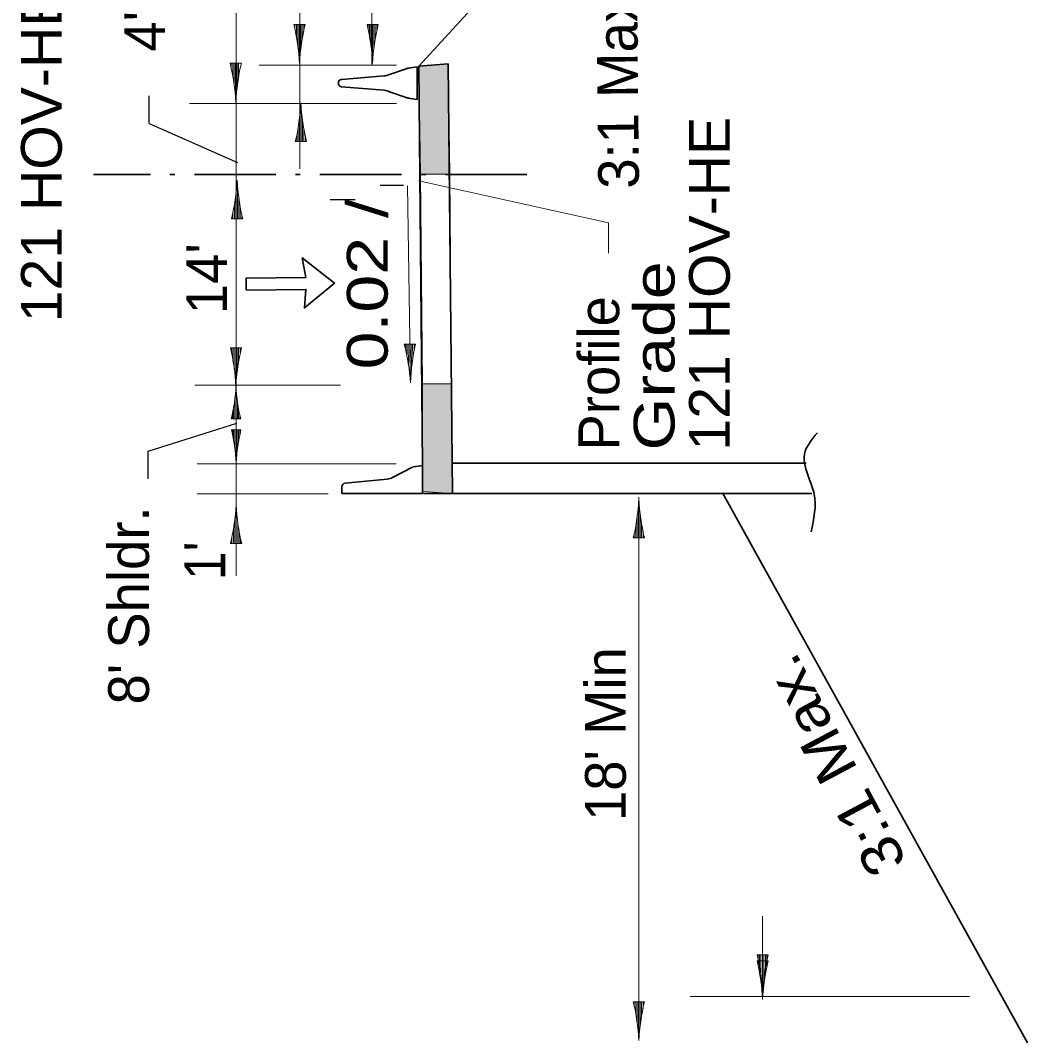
# Model space of a CAD drawing. Extents: x 2363427 to 2368559, y 6957299 to 6980140.
# Drawn here: x 2365078.3 to 2365424.5, y 6964606.4 to 6964957.4 of the extents above; entities that cross this region are included whole.
import ezdxf
from ezdxf.enums import TextEntityAlignment as Align

# ---------------------------------------------------------------- set-up
doc = ezdxf.new("R2010")
doc.units = 0
doc.header["$LTSCALE"] = 5.6
doc.linetypes.add('DOT_DASHED', pattern=[7.7, 5, -1.2, 0.3, -1.2])
doc.layers.add('3', color=7, linetype='Continuous', lineweight=35)
doc.layers.add('4', color=7, linetype='Continuous', lineweight=13)

msp = doc.modelspace()

# ---------------------------------------------------------------- hatches: boundary and pattern name
at = {"layer": '3'}
for points in [[(2365215.222, 6964941.608), (2365225.378, 6964942.446), (2365225.904, 6964904.586), (2365215.863, 6964904.586)], [(2365216.491, 6964795.461), (2365226.814, 6964794.766), (2365226.531, 6964832.463), (2365216.491, 6964832.463)]]:
    msp.add_hatch(color=256, dxfattribs=at).paths.add_polyline_path(points)

# ---------------------------------------------------------------- linework, layer by layer
at = {"layer": '3', "lineweight": 13}
for p, q in [((2365174.345, 6964906.409), (2365174.345, 6965009.032)), ((2365199.111, 6964942.054), (2365199.111, 6964990.853)), ((2365152.449, 6964766.446), (2365152.449, 6964981.39)), ((2365280.421, 6964887.841), (2365215.226, 6964902.184)), ((2365280.421, 6964887.841), (2365280.421, 6964877.381))]:
    msp.add_line(p, q, dxfattribs=at)
at = {"layer": '3'}
for p, q in [((2365259.357, 6964989.862), (2365215.222, 6964941.608)), ((2365205.179, 6964938.845), (2365211.293, 6964940.886)), ((2365211.457, 6964940.952), (2365211.467, 6964940.976)), ((2365214.73, 6964941.464), (2365211.467, 6964940.976)), ((2365214.73, 6964941.464), (2365211.664, 6964941.006)), ((2365214.73, 6964941.464), (2365214.73, 6964935.84)), ((2365226.814, 6964794.766), (2365225.378, 6964942.446)), ((2365187.66, 6964936.24), (2365187.66, 6964935.84)), ((2365187.66, 6964935.439), (2365187.66, 6964935.84)), ((2365203.391, 6964938.316), (2365188.687, 6964937.081)), ((2365214.73, 6964930.214), (2365214.73, 6964935.84)), ((2365203.391, 6964933.363), (2365188.687, 6964934.598)), ((2365205.179, 6964932.834), (2365211.293, 6964930.792)), ((2365211.457, 6964930.728), (2365211.467, 6964930.702)), ((2365214.73, 6964930.214), (2365211.467, 6964930.702)), ((2365214.73, 6964930.214), (2365211.664, 6964930.674)), ((2365176.449, 6964864.892), (2365155.944, 6964864.696)), ((2365206.257, 6964800.286), (2365213.091, 6964803.8)), ((2365213.259, 6964803.866), (2365213.269, 6964803.892)), ((2365216.557, 6964804.384), (2365216.557, 6964794.754)), ((2365226.713, 6964805.222), (2365348.364, 6964805.222)), ((2365189.943, 6964798.292), (2365204.426, 6964799.744)), ((2365188.837, 6964794.754), (2365188.837, 6964797.068)), ((2365216.557, 6964794.754), (2365188.837, 6964794.754)), ((2365226.892, 6964794.766), (2365216.889, 6964794.766)), ((2365226.892, 6964794.766), (2365350.332, 6964794.766)), ((2365424.46, 6964605.922), (2365319.67, 6964794.944))]:
    msp.add_line(p, q, dxfattribs=at)
at = {"layer": '3', "linetype": 'DOT_DASHED'}
msp.add_line((2365252.369, 6964904.416), (2365103.492, 6964904.416), dxfattribs=at)
at = {"layer": '3', "lineweight": 13}
for points in [[(2365215.222, 6964941.608), (2365225.378, 6964942.446), (2365225.904, 6964904.586), (2365215.863, 6964904.586)], [(2365216.491, 6964832.463), (2365226.531, 6964832.463), (2365225.904, 6964904.586), (2365215.863, 6964904.586)], [(2365216.491, 6964795.461), (2365226.814, 6964794.766), (2365226.531, 6964832.463), (2365216.491, 6964832.463)]]:
    msp.add_lwpolyline(points, close=True, dxfattribs=at)
at = {"layer": '3'}
for points in [[(2365216.557, 6964804.384), (2365215.222, 6964941.608), (2365225.378, 6964942.446)], [(2365176.449, 6964864.892), (2365175.917, 6964858.576), (2365186.304, 6964867.112), (2365175.204, 6964875.714), (2365176.412, 6964868.986)], [(2365176.412, 6964868.986), (2365155.907, 6964868.792), (2365155.944, 6964864.696)], [(2365213.471, 6964803.922), (2365216.611, 6964804.392), (2365213.269, 6964803.892)]]:
    msp.add_lwpolyline(points, dxfattribs=at)
msp.add_lwpolyline([(2365186.304, 6964867.112), (2365175.917, 6964858.576), (2365176.449, 6964864.892), (2365155.944, 6964864.696), (2365155.907, 6964868.792), (2365176.412, 6964868.986), (2365175.204, 6964875.714)], close=True, dxfattribs=at)
for centre, radius, start, end in [((2365211.842, 6964939.82), 1.2, 98.51269, 117.22516), ((2365188.807, 6964935.888), 1.2, 95.72178, 162.90786), ((2365202.891, 6964943.292), 5, 275.73538, 297.22872), ((2365188.807, 6964935.792), 1.2, 197.09214, 264.27822), ((2365202.891, 6964928.388), 5, 62.77128, 84.26462), ((2365211.842, 6964931.86), 1.2, 242.77484, 261.48731), ((2365203.915, 6964804.839), 5.12, 275.73538, 297.22872), ((2365190.066, 6964797.069), 1.229, 95.72178, 180)]:
    msp.add_arc(centre, radius, start, end, dxfattribs=at)
msp.add_spline([(2365350.035, 6964781.584), (2365351.147, 6964794.552), (2365349.293, 6964800.11), (2365347.81, 6964808.262), (2365352.259, 6964815.672)], degree=3, dxfattribs=at)
at = {"layer": '4'}
for p, q in [((2365172.333, 6964955.924), (2365176.163, 6964955.924)), ((2365172.683, 6964955.924), (2365172.683, 6964954.338)), ((2365173.183, 6964955.924), (2365173.183, 6964951.647)), ((2365173.683, 6964955.924), (2365173.683, 6964948.574)), ((2365174.183, 6964955.924), (2365174.183, 6964943.36)), ((2365174.683, 6964955.924), (2365174.683, 6964947.314)), ((2365175.183, 6964955.924), (2365175.183, 6964951.062)), ((2365175.683, 6964955.924), (2365175.683, 6964953.542)), ((2365197.459, 6964955.924), (2365201.289, 6964955.924)), ((2365197.809, 6964955.924), (2365197.809, 6964954.338)), ((2365198.309, 6964955.924), (2365198.309, 6964951.647)), ((2365198.809, 6964955.924), (2365198.809, 6964948.574)), ((2365199.309, 6964955.924), (2365199.309, 6964943.36)), ((2365199.809, 6964955.924), (2365199.809, 6964947.314)), ((2365200.309, 6964955.924), (2365200.309, 6964951.062)), ((2365200.809, 6964955.924), (2365200.809, 6964953.542)), ((2365150.437, 6964942.648), (2365154.267, 6964942.648)), ((2365150.787, 6964942.648), (2365150.787, 6964941.062)), ((2365151.287, 6964942.648), (2365151.287, 6964938.371)), ((2365151.787, 6964942.648), (2365151.787, 6964935.298)), ((2365152.287, 6964942.648), (2365152.287, 6964930.084)), ((2365152.787, 6964942.648), (2365152.787, 6964934.038)), ((2365153.287, 6964942.648), (2365153.287, 6964937.786)), ((2365207.597, 6964942.054), (2365160.427, 6964942.054)), ((2365207.597, 6964928.777), (2365136.481, 6964928.777)), ((2365174.781, 6964915.704), (2365174.781, 6964928.268)), ((2365174.281, 6964915.704), (2365174.281, 6964924.314)), ((2365175.281, 6964915.704), (2365175.281, 6964923.054)), ((2365173.281, 6964915.704), (2365173.281, 6964918.086)), ((2365173.781, 6964915.704), (2365173.781, 6964920.566)), ((2365175.781, 6964915.704), (2365175.781, 6964919.981)), ((2365176.631, 6964915.704), (2365172.801, 6964915.704)), ((2365176.281, 6964915.704), (2365176.281, 6964917.289)), ((2365152.885, 6964889.152), (2365152.885, 6964901.716)), ((2365212.4, 6964832.806), (2365211.326, 6964900.522)), ((2365152.385, 6964889.152), (2365152.385, 6964897.762)), ((2365151.885, 6964889.152), (2365151.885, 6964894.014)), ((2365153.385, 6964889.152), (2365153.385, 6964896.502)), ((2365151.385, 6964889.152), (2365151.385, 6964891.534)), ((2365153.885, 6964889.152), (2365153.885, 6964893.428)), ((2365154.385, 6964889.152), (2365154.385, 6964890.736)), ((2365154.735, 6964889.152), (2365150.905, 6964889.152)), ((2365150.491, 6964844.872), (2365154.321, 6964844.872)), ((2365150.841, 6964844.872), (2365150.841, 6964843.287)), ((2365151.341, 6964844.872), (2365151.341, 6964840.596)), ((2365151.841, 6964844.872), (2365151.841, 6964837.522)), ((2365152.341, 6964844.872), (2365152.341, 6964832.308)), ((2365152.841, 6964844.872), (2365152.841, 6964836.262)), ((2365153.341, 6964844.872), (2365153.341, 6964840.01)), ((2365153.841, 6964844.872), (2365153.841, 6964842.49)), ((2365210.274, 6964846.084), (2365214.103, 6964846.146)), ((2365210.624, 6964846.09), (2365210.649, 6964844.506)), ((2365211.124, 6964846.098), (2365211.192, 6964841.822)), ((2365211.624, 6964846.106), (2365211.74, 6964838.758)), ((2365212.124, 6964846.114), (2365212.323, 6964833.552)), ((2365212.624, 6964846.122), (2365212.76, 6964837.514)), ((2365213.123, 6964846.13), (2365213.201, 6964841.268)), ((2365213.623, 6964846.138), (2365213.661, 6964843.756)), ((2365188.367, 6964831.96), (2365138.254, 6964831.96)), ((2365152.472, 6964820.394), (2365152.472, 6964831.074)), ((2365152.047, 6964820.394), (2365152.047, 6964827.712)), ((2365151.622, 6964820.394), (2365151.622, 6964824.526)), ((2365152.897, 6964820.394), (2365152.897, 6964826.642)), ((2365153.322, 6964820.394), (2365153.322, 6964824.03)), ((2365154.044, 6964820.394), (2365150.789, 6964820.394)), ((2365151.197, 6964820.394), (2365151.197, 6964822.418)), ((2365153.747, 6964820.394), (2365153.747, 6964821.742)), ((2365150.879, 6964816.604), (2365154.135, 6964816.604)), ((2365151.177, 6964816.604), (2365151.177, 6964815.257)), ((2365151.601, 6964816.604), (2365151.601, 6964812.97)), ((2365152.027, 6964816.604), (2365152.027, 6964810.357)), ((2365152.451, 6964816.604), (2365152.451, 6964805.924)), ((2365152.877, 6964816.604), (2365152.877, 6964809.286)), ((2365153.301, 6964816.604), (2365153.301, 6964812.472)), ((2365153.727, 6964816.604), (2365153.727, 6964814.58)), ((2365207.473, 6964804.942), (2365139.048, 6964804.942)), ((2365184.059, 6964794.678), (2365139.048, 6964794.678)), ((2365290.803, 6964779.513), (2365290.803, 6964792.077)), ((2365290.869, 6964606.718), (2365290.868, 6964793.518)), ((2365152.526, 6964777.568), (2365152.526, 6964790.132)), ((2365152.026, 6964777.568), (2365152.026, 6964786.178)), ((2365153.026, 6964777.568), (2365153.026, 6964784.918)), ((2365290.303, 6964779.513), (2365290.303, 6964786.863)), ((2365291.303, 6964779.513), (2365291.303, 6964788.122)), ((2365151.526, 6964777.568), (2365151.526, 6964782.43)), ((2365153.526, 6964777.568), (2365153.526, 6964781.844)), ((2365289.803, 6964779.513), (2365289.803, 6964783.79)), ((2365291.803, 6964779.513), (2365291.803, 6964784.375)), ((2365292.303, 6964779.513), (2365292.303, 6964781.894)), ((2365151.026, 6964777.568), (2365151.026, 6964779.95)), ((2365154.026, 6964777.568), (2365154.026, 6964779.152)), ((2365288.953, 6964779.513), (2365292.783, 6964779.513)), ((2365289.303, 6964779.513), (2365289.303, 6964781.098)), ((2365154.376, 6964777.568), (2365150.546, 6964777.568)), ((2365333.404, 6964621.277), (2365333.404, 6964649.497)), ((2365331.489, 6964636.229), (2365335.319, 6964636.229)), ((2365331.489, 6964634.139), (2365335.319, 6964634.139)), ((2365331.839, 6964636.229), (2365331.839, 6964634.645)), ((2365331.839, 6964634.139), (2365331.839, 6964632.553)), ((2365332.339, 6964636.229), (2365332.339, 6964631.953)), ((2365332.339, 6964634.139), (2365332.339, 6964629.861)), ((2365332.839, 6964636.229), (2365332.839, 6964628.879)), ((2365332.839, 6964634.139), (2365332.839, 6964626.789)), ((2365333.339, 6964636.229), (2365333.339, 6964623.665)), ((2365333.339, 6964634.139), (2365333.339, 6964621.575)), ((2365333.839, 6964636.229), (2365333.839, 6964627.619)), ((2365333.839, 6964634.139), (2365333.839, 6964625.529)), ((2365334.339, 6964636.229), (2365334.339, 6964631.367)), ((2365334.339, 6964634.139), (2365334.339, 6964629.277)), ((2365334.839, 6964636.229), (2365334.839, 6964633.847)), ((2365334.839, 6964634.139), (2365334.839, 6964631.757)), ((2365288.954, 6964620.03), (2365292.784, 6964620.03)), ((2365289.304, 6964620.03), (2365289.304, 6964618.445)), ((2365289.804, 6964620.03), (2365289.804, 6964615.754)), ((2365290.304, 6964620.03), (2365290.304, 6964612.68)), ((2365290.804, 6964620.03), (2365290.804, 6964607.466)), ((2365291.304, 6964620.03), (2365291.304, 6964611.42)), ((2365291.804, 6964620.03), (2365291.804, 6964615.168)), ((2365292.304, 6964620.03), (2365292.304, 6964617.648)), ((2365404.537, 6964621.87), (2365308.474, 6964621.87))]:
    msp.add_line(p, q, dxfattribs=at)
at = {"layer": '4', "lineweight": 25}
for p, q in [((2365122.636, 6964921.9), (2365122.636, 6964931.486)), ((2365122.636, 6964921.9), (2365152.889, 6964908.562)), ((2365201.952, 6964900.798), (2365209.984, 6964900.798)), ((2365193.381, 6964895.659), (2365184.81, 6964895.659)), ((2365122.227, 6964809.33), (2365152.68, 6964818.904)), ((2365122.227, 6964799.746), (2365122.227, 6964809.33))]:
    msp.add_line(p, q, dxfattribs=at)
at = {"layer": '4'}
for centre, radius, start, end in [((2365102.125, 6964939.03), 72.212, 2.84356, 13.52961), ((2365246.372, 6964939.03), 72.212, 166.47039, 177.15644), ((2365127.252, 6964939.03), 72.212, 2.84356, 13.52961), ((2365271.499, 6964939.03), 72.212, 166.47039, 177.15644), ((2365080.229, 6964925.754), 72.212, 2.84356, 13.52961), ((2365224.476, 6964925.754), 72.212, 166.47039, 177.15644), ((2365102.592, 6964932.599), 72.212, 346.47039, 357.15644), ((2365246.839, 6964932.599), 72.212, 182.84356, 193.52961), ((2365080.696, 6964906.046), 72.212, 346.47039, 357.15644), ((2365224.943, 6964906.046), 72.212, 182.84356, 193.52961), ((2365080.283, 6964827.979), 72.212, 2.84356, 13.52961), ((2365224.53, 6964827.979), 72.212, 166.47039, 177.15644), ((2365140.343, 6964828.08), 72.212, 3.7522, 14.43825), ((2365284.572, 6964830.368), 72.212, 167.37903, 178.06508), ((2365091.111, 6964834.755), 61.381, 346.47039, 357.15644), ((2365213.721, 6964834.755), 61.381, 182.84356, 193.52961), ((2365091.203, 6964802.245), 61.381, 2.84356, 13.52961), ((2365213.813, 6964802.245), 61.381, 166.47039, 177.15644), ((2365218.745, 6964796.408), 72.212, 346.47039, 357.15644), ((2365362.992, 6964796.408), 72.212, 182.84356, 193.52961), ((2365080.337, 6964794.462), 72.212, 346.47039, 357.15644), ((2365224.584, 6964794.462), 72.212, 182.84356, 193.52961), ((2365261.282, 6964619.336), 72.212, 2.84356, 13.52961), ((2365261.282, 6964617.245), 72.212, 2.84356, 13.52961), ((2365405.529, 6964619.336), 72.212, 166.47039, 177.15644), ((2365405.529, 6964617.245), 72.212, 166.47039, 177.15644), ((2365218.746, 6964603.137), 72.212, 2.84356, 13.52961), ((2365362.993, 6964603.137), 72.212, 166.47039, 177.15644)]:
    msp.add_arc(centre, radius, start, end, dxfattribs=at)

# ---------------------------------------------------------------- texts
for s, rotation, p in [("4' Shldr.", 90, (2365128.003, 6964980.691)), ('3:1 Max.', 90.562, (2365290.595, 6964935.485)), ("14'", 90, (2365149.382, 6964868.597)), ("8' Shldr.", 90, (2365122.526, 6964756.282)), ("18' Min", 90, (2365286.392, 6964712.046))]:
    msp.add_text(s, height=14, rotation=rotation, dxfattribs=at).set_placement(p, align=Align.CENTER)
for s, rotation, width, p in [('121 HOV-HE', 90, 1.05, (2365092.551, 6964910.964)), ('0.02 /', 90, 1.25, (2365204.543, 6964866.7)), ("1'", 90, 0.95, (2365148.71, 6964771.624)), ('3:1 Max.', 118.062, 1.15, (2365363.868, 6964704.58))]:
    msp.add_text(s, height=14, rotation=rotation, dxfattribs=dict(at, width=width)).set_placement(p, align=Align.CENTER)
for s, width, p in [('121 HOV-HE', 1.05, (2365322.126, 6964809.532)), ('Grade ', 1.25, (2365303.126, 6964809.532))]:
    msp.add_text(s, height=14, rotation=90, dxfattribs=dict(at, width=width)).set_placement(p)
msp.add_text('Profile ', height=14, rotation=90, dxfattribs=at).set_placement((2365284.126, 6964809.532))

doc.saveas('drawing.dxf')
